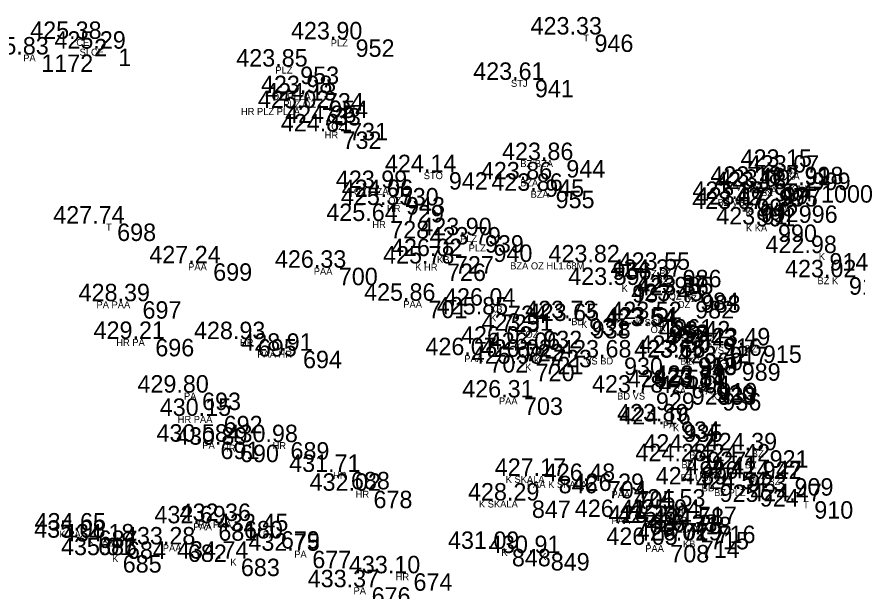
# Model space of a CAD drawing. Extents: x -639390 to -639075, y -1138747 to -1138358.
# Drawn here: x -639158.84 to -639122.71, y -1138672.58 to -1138647.88 of the extents above; entities that cross this region are included whole.
import ezdxf

# ---------------------------------------------------------------- set-up
doc = ezdxf.new("R2010")
doc.units = 0
for name, color, linetype in [('Vrstva 11', 7, 'Continuous'), ('Vrstva 12', 7, 'Continuous'), ('Vrstva 13', 7, 'Continuous'), ('Vrstva 57', 7, 'Continuous')]:
    doc.layers.add(name, color=color, linetype=linetype)

msp = doc.modelspace()

# ---------------------------------------------------------------- linework, layer by layer
at = {"layer": 'Vrstva 11'}
for p, q in [((-639134.28, -1138648.64), (-639134.28, -1138648.64)), ((-639155.79, -1138648.83), (-639155.79, -1138648.83)), ((-639144.55, -1138648.85), (-639144.55, -1138648.85)), ((-639154.75, -1138649.25), (-639154.75, -1138649.25)), ((-639158.06, -1138649.5), (-639158.06, -1138649.5)), ((-639146.93, -1138650.02), (-639146.93, -1138650.02)), ((-639136.84, -1138650.59), (-639136.84, -1138650.59)), ((-639145.87, -1138651.16), (-639145.87, -1138651.16)), ((-639145.69, -1138651.48), (-639145.69, -1138651.48)), ((-639146, -1138651.8), (-639146, -1138651.8)), ((-639144.83, -1138652.44), (-639144.83, -1138652.44)), ((-639145.11, -1138652.81), (-639145.11, -1138652.81)), ((-639135.49, -1138654.04), (-639135.49, -1138654.04)), ((-639125.25, -1138654.33), (-639125.25, -1138654.33)), ((-639140.54, -1138654.56), (-639140.54, -1138654.56)), ((-639136.4, -1138654.87), (-639136.4, -1138654.87)), ((-639124.94, -1138654.58), (-639124.94, -1138654.58)), ((-639142.65, -1138655.24), (-639142.65, -1138655.24)), ((-639126.55, -1138655.06), (-639126.55, -1138655.06)), ((-639126.19, -1138655.19), (-639126.19, -1138655.19)), ((-639124.54, -1138655.12), (-639124.54, -1138655.12)), ((-639135.95, -1138655.36), (-639135.95, -1138655.36)), ((-639126.35, -1138655.29), (-639126.35, -1138655.29)), ((-639142.43, -1138655.97), (-639142.43, -1138655.97)), ((-639142.38, -1138655.63), (-639142.38, -1138655.63)), ((-639127.32, -1138655.71), (-639127.32, -1138655.71)), ((-639127.18, -1138655.96), (-639127.18, -1138655.96)), ((-639127.33, -1138656.14), (-639127.33, -1138656.14)), ((-639125.5, -1138655.99), (-639125.5, -1138655.99)), ((-639143.06, -1138656.66), (-639143.06, -1138656.66)), ((-639154.8, -1138656.77), (-639154.8, -1138656.77)), ((-639126.39, -1138656.81), (-639126.39, -1138656.81)), ((-639138.99, -1138657.27), (-639138.99, -1138657.27)), ((-639138.62, -1138657.67), (-639138.62, -1138657.67)), ((-639124.18, -1138658.04), (-639124.18, -1138658.04)), ((-639150.67, -1138658.48), (-639150.67, -1138658.48)), ((-639140.62, -1138658.49), (-639140.62, -1138658.49)), ((-639140.28, -1138658.17), (-639140.28, -1138658.17)), ((-639133.51, -1138658.44), (-639133.51, -1138658.44)), ((-639145.27, -1138658.67), (-639145.27, -1138658.67)), ((-639130.49, -1138658.76), (-639130.49, -1138658.76)), ((-639130.84, -1138659.06), (-639130.84, -1138659.06)), ((-639123.34, -1138659.08), (-639123.34, -1138659.08)), ((-639132.66, -1138659.41), (-639132.66, -1138659.41)), ((-639129.74, -1138659.74), (-639129.74, -1138659.74)), ((-639129.67, -1138659.85), (-639129.67, -1138659.85)), ((-639153.71, -1138660.11), (-639153.71, -1138660.11)), ((-639141.42, -1138660.09), (-639141.42, -1138660.09)), ((-639138, -1138660.3), (-639138, -1138660.3)), ((-639129.95, -1138660.1), (-639129.95, -1138660.1)), ((-639138.31, -1138660.68), (-639138.31, -1138660.68)), ((-639134.51, -1138660.84), (-639134.51, -1138660.84)), ((-639134.4, -1138660.96), (-639134.4, -1138660.96)), ((-639130.85, -1138660.88), (-639130.85, -1138660.88)), ((-639136.48, -1138661.38), (-639136.48, -1138661.38)), ((-639131.1, -1138661.18), (-639131.1, -1138661.18)), ((-639131.03, -1138661.11), (-639131.03, -1138661.11)), ((-639153.16, -1138661.73), (-639153.16, -1138661.73)), ((-639148.75, -1138661.74), (-639148.75, -1138661.74)), ((-639128.76, -1138661.71), (-639128.76, -1138661.71)), ((-639137.27, -1138661.94), (-639137.27, -1138661.94)), ((-639128.48, -1138662.07), (-639128.48, -1138662.07)), ((-639127.04, -1138662.01), (-639127.04, -1138662.01)), ((-639146.81, -1138662.24), (-639146.81, -1138662.24)), ((-639138.8, -1138662.43), (-639138.8, -1138662.43)), ((-639136.06, -1138662.2), (-639136.06, -1138662.2)), ((-639129.57, -1138662.33), (-639129.57, -1138662.33)), ((-639136.81, -1138662.8), (-639136.81, -1138662.8)), ((-639136.43, -1138662.5), (-639136.43, -1138662.5)), ((-639133.01, -1138662.53), (-639133.01, -1138662.53)), ((-639129.83, -1138662.54), (-639129.83, -1138662.54)), ((-639129.8, -1138662.52), (-639129.8, -1138662.52)), ((-639127.95, -1138662.78), (-639127.95, -1138662.78)), ((-639130.1, -1138663.81), (-639130.1, -1138663.81)), ((-639129.06, -1138663.72), (-639129.06, -1138663.72)), ((-639128.99, -1138663.81), (-639128.99, -1138663.81)), ((-639128.95, -1138663.62), (-639128.95, -1138663.62)), ((-639151.15, -1138664.04), (-639151.15, -1138664.04)), ((-639137.31, -1138664.25), (-639137.31, -1138664.25)), ((-639131.64, -1138664.04), (-639131.64, -1138664.04)), ((-639128.78, -1138664.06), (-639128.78, -1138664.06)), ((-639150.22, -1138665.04), (-639150.22, -1138665.04)), ((-639130.56, -1138665.28), (-639130.56, -1138665.28)), ((-639130.45, -1138665.41), (-639130.45, -1138665.41)), ((-639150.36, -1138666.15), (-639150.36, -1138666.15)), ((-639149.52, -1138666.28), (-639149.52, -1138666.28)), ((-639147.35, -1138666.17), (-639147.35, -1138666.17)), ((-639129.43, -1138666.58), (-639129.43, -1138666.58)), ((-639126.75, -1138666.52), (-639126.75, -1138666.52)), ((-639129.77, -1138666.99), (-639129.77, -1138666.99)), ((-639127.05, -1138667), (-639127.05, -1138667)), ((-639144.75, -1138667.45), (-639144.75, -1138667.45)), ((-639135.82, -1138667.62), (-639135.82, -1138667.62)), ((-639133.71, -1138667.84), (-639133.71, -1138667.84)), ((-639127.7, -1138667.55), (-639127.7, -1138667.55)), ((-639125.68, -1138667.72), (-639125.68, -1138667.72)), ((-639143.78, -1138668.26), (-639143.78, -1138668.26)), ((-639128.9, -1138667.99), (-639128.9, -1138667.99)), ((-639127.17, -1138668.19), (-639127.17, -1138668.19)), ((-639132.47, -1138668.27), (-639132.47, -1138668.27)), ((-639136.97, -1138668.68), (-639136.97, -1138668.68)), ((-639129.83, -1138668.94), (-639129.83, -1138668.94)), ((-639124.83, -1138668.71), (-639124.83, -1138668.71)), ((-639150.45, -1138669.66), (-639150.45, -1138669.66)), ((-639149.35, -1138669.56), (-639149.35, -1138669.56)), ((-639132.47, -1138669.39), (-639132.47, -1138669.39)), ((-639131.03, -1138669.64), (-639131.03, -1138669.64)), ((-639130.49, -1138669.64), (-639130.49, -1138669.64)), ((-639130.06, -1138669.38), (-639130.06, -1138669.38)), ((-639155.6, -1138669.97), (-639155.6, -1138669.97)), ((-639147.76, -1138670), (-639147.76, -1138670)), ((-639129.31, -1138670.03), (-639129.31, -1138670.03)), ((-639129.03, -1138669.76), (-639129.03, -1138669.76)), ((-639155.62, -1138670.28), (-639155.62, -1138670.28)), ((-639129.71, -1138670.4), (-639129.71, -1138670.4)), ((-639154.38, -1138670.44), (-639154.38, -1138670.44)), ((-639151.76, -1138670.57), (-639151.76, -1138670.57)), ((-639137.83, -1138670.76), (-639137.83, -1138670.76)), ((-639131.02, -1138670.59), (-639131.02, -1138670.59)), ((-639154.56, -1138671.03), (-639154.56, -1138671.03)), ((-639146.41, -1138670.84), (-639146.41, -1138670.84)), ((-639136.16, -1138670.94), (-639136.16, -1138670.94)), ((-639149.48, -1138671.18), (-639149.48, -1138671.18)), ((-639142.06, -1138671.81), (-639142.06, -1138671.81)), ((-639143.86, -1138672.41), (-639143.86, -1138672.41))]:
    msp.add_line(p, q, dxfattribs=at)

# ---------------------------------------------------------------- texts
at = {"layer": 'Vrstva 12'}
for s, p in [('423.33 ', (-639136.749, -1138648.64)), ('425.38 ', (-639158.259, -1138648.83)), ('423.90 ', (-639147.049, -1138648.85)), ('425.83 ', (-639160.529, -1138649.5)), ('425.29 ', (-639157.219, -1138649.25)), ('423.85 ', (-639149.4, -1138650.02)), ('423.61 ', (-639139.215, -1138650.59)), ('423.98 ', (-639148.339, -1138651.16)), ('424.13 ', (-639148.159, -1138651.48)), ('425.02 ', (-639148.469, -1138651.8)), ('424.25 ', (-639147.3, -1138652.44)), ('424.81 ', (-639147.485, -1138652.81)), ('423.86 ', (-639137.976, -1138654.04)), ('424.14 ', (-639143.009, -1138654.56)), ('423.15 ', (-639127.72, -1138654.33)), ('423.86 ', (-639138.886, -1138654.87)), ('423.07 ', (-639127.409, -1138654.58)), ('423.99 ', (-639145.119, -1138655.24)), ('423.18 ', (-639129.019, -1138655.06)), ('423.13 ', (-639128.819, -1138655.29)), ('423.09 ', (-639128.659, -1138655.19)), ('422.91 ', (-639126.915, -1138655.12)), ('424.06 ', (-639144.866, -1138655.63)), ('423.86 ', (-639138.436, -1138655.36)), ('425.35 ', (-639144.9, -1138655.97)), ('423.18 ', (-639129.789, -1138655.71)), ('423.17 ', (-639129.649, -1138655.96)), ('422.97 ', (-639127.969, -1138655.99)), ('423.07 ', (-639129.799, -1138656.14)), ('425.64 ', (-639145.529, -1138656.66)), ('427.74 ', (-639157.269, -1138656.77)), ('423.01 ', (-639128.765, -1138656.81)), ('423.90 ', (-639141.489, -1138657.27)), ('423.79 ', (-639141.089, -1138657.67)), ('426.02 ', (-639142.749, -1138658.17)), ('422.98 ', (-639126.649, -1138658.04)), ('427.24 ', (-639153.139, -1138658.48)), ('425.78 ', (-639143.089, -1138658.49)), ('423.82 ', (-639135.979, -1138658.44)), ('426.33 ', (-639147.739, -1138658.67)), ('423.55 ', (-639132.96, -1138658.76)), ('424.37 ', (-639133.309, -1138659.06)), ('423.02 ', (-639125.809, -1138659.08)), ('423.59 ', (-639135.129, -1138659.41)), ('423.37 ', (-639132.209, -1138659.74)), ('423.36 ', (-639132.156, -1138659.85)), ('428.39 ', (-639156.179, -1138660.11)), ('425.86 ', (-639143.906, -1138660.09)), ('426.04 ', (-639140.469, -1138660.3)), ('423.43 ', (-639132.419, -1138660.1)), ('425.85 ', (-639140.78, -1138660.68)), ('423.73 ', (-639136.979, -1138660.84)), ('423.65 ', (-639136.87, -1138660.96)), ('423.52 ', (-639133.319, -1138660.88)), ('423.91 ', (-639138.855, -1138661.38)), ('423.54 ', (-639133.569, -1138661.18)), ('423.54 ', (-639133.499, -1138661.11)), ('429.21 ', (-639155.535, -1138661.73)), ('428.93 ', (-639151.219, -1138661.74)), ('423.42 ', (-639131.229, -1138661.71)), ('426.02 ', (-639139.739, -1138661.94)), ('423.43 ', (-639130.949, -1138662.07)), ('423.49 ', (-639129.509, -1138662.01)), ('428.91 ', (-639149.185, -1138662.24)), ('426.07 ', (-639141.269, -1138662.43)), ('426.02 ', (-639138.899, -1138662.5)), ('426.06 ', (-639138.546, -1138662.2)), ('423.56 ', (-639132.286, -1138662.52)), ('423.50 ', (-639132.069, -1138662.33)), ('425.98 ', (-639139.279, -1138662.8)), ('423.68 ', (-639135.479, -1138662.53)), ('423.65 ', (-639132.3, -1138662.54)), ('423.42 ', (-639130.419, -1138662.78)), ('423.75 ', (-639132.57, -1138663.81)), ('423.84 ', (-639131.459, -1138663.81)), ('423.81 ', (-639131.435, -1138663.72)), ('423.79 ', (-639131.419, -1138663.62)), ('429.80 ', (-639153.649, -1138664.04)), ('426.31 ', (-639139.685, -1138664.25)), ('423.78 ', (-639134.109, -1138664.04)), ('424.04 ', (-639131.249, -1138664.06)), ('430.15 ', (-639152.69, -1138665.04)), ('423.89 ', (-639133.029, -1138665.28)), ('424.16 ', (-639132.936, -1138665.41)), ('430.58 ', (-639152.829, -1138666.15)), ('430.89 ', (-639151.989, -1138666.28)), ('430.98 ', (-639149.819, -1138666.17)), ('424.22 ', (-639131.899, -1138666.58)), ('424.39 ', (-639129.219, -1138666.52)), ('424.28 ', (-639132.239, -1138666.99)), ('424.42 ', (-639129.519, -1138667)), ('431.71 ', (-639147.125, -1138667.45)), ('424.41 ', (-639130.075, -1138667.55)), ('427.17 ', (-639138.289, -1138667.62)), ('426.48 ', (-639136.179, -1138667.84)), ('424.47 ', (-639128.149, -1138667.72)), ('432.02 ', (-639146.249, -1138668.26)), ('426.29 ', (-639134.939, -1138668.27)), ('424.39 ', (-639131.369, -1138667.99)), ('424.54 ', (-639129.639, -1138668.19)), ('428.29 ', (-639139.439, -1138668.68)), ('424.53 ', (-639132.299, -1138668.94)), ('424.47 ', (-639127.299, -1138668.71)), ('426.41 ', (-639134.845, -1138669.39)), ('425.94 ', (-639132.529, -1138669.38)), ('432.69 ', (-639152.919, -1138669.66)), ('432.36 ', (-639151.836, -1138669.56)), ('426.11 ', (-639133.405, -1138669.64)), ('425.60 ', (-639132.989, -1138669.64)), ('434.65 ', (-639158.07, -1138669.97)), ('432.45 ', (-639150.23, -1138670)), ('426.33 ', (-639131.779, -1138670.03)), ('424.58 ', (-639131.499, -1138669.76)), ('435.08 ', (-639158.089, -1138670.28)), ('434.18 ', (-639156.849, -1138670.44)), ('426.02 ', (-639132.179, -1138670.4)), ('433.28 ', (-639154.229, -1138670.57)), ('431.09 ', (-639140.299, -1138670.76)), ('426.05 ', (-639133.49, -1138670.59)), ('435.01 ', (-639156.935, -1138671.03)), ('434.74 ', (-639151.949, -1138671.18)), ('432.75 ', (-639148.88, -1138670.84)), ('430.91 ', (-639138.535, -1138670.94)), ('433.10 ', (-639144.559, -1138671.81)), ('433.37 ', (-639146.329, -1138672.41))]:
    msp.add_text(s, height=0.75, dxfattribs=at).set_placement(p)
at = {"layer": 'Vrstva 13'}
for s, p in [(' 946', (-639134.28, -1138649.39)), (' 2', (-639155.79, -1138649.58)), (' 952', (-639144.55, -1138649.6)), (' 1', (-639154.75, -1138650)), (' 1172', (-639158.06, -1138650.25)), (' 953', (-639146.93, -1138650.77)), (' 941', (-639136.84, -1138651.34)), (' 734', (-639145.87, -1138651.91)), (' 954', (-639145.69, -1138652.23)), (' 733', (-639146, -1138652.55)), (' 731', (-639144.83, -1138653.19)), (' 732', (-639145.11, -1138653.56)), (' 944', (-639135.49, -1138654.79)), (' 998', (-639125.25, -1138655.08)), (' 942', (-639140.54, -1138655.31)), (' 945', (-639136.4, -1138655.62)), (' 999', (-639124.94, -1138655.33)), (' 730', (-639142.65, -1138655.99)), (' 994', (-639126.55, -1138655.81)), (' 997', (-639126.19, -1138655.94)), (' 1000', (-639124.54, -1138655.87)), (' 943', (-639142.38, -1138656.38)), (' 955', (-639135.95, -1138656.11)), (' 995', (-639126.35, -1138656.04)), (' 729', (-639142.43, -1138656.72)), (' 993', (-639127.32, -1138656.46)), (' 992', (-639127.18, -1138656.71)), (' 996', (-639125.5, -1138656.74)), (' 991', (-639127.33, -1138656.89)), (' 728', (-639143.06, -1138657.41)), (' 698', (-639154.8, -1138657.52)), (' 990', (-639126.39, -1138657.56)), (' 939', (-639138.99, -1138658.02)), (' 940', (-639138.62, -1138658.42)), (' 914', (-639124.18, -1138658.79)), (' 699', (-639150.67, -1138659.23)), (' 726', (-639140.62, -1138659.24)), (' 727', (-639140.28, -1138658.92)), (' 956', (-639133.51, -1138659.19)), (' 700', (-639145.27, -1138659.42)), (' 986', (-639130.49, -1138659.51)), (' 985', (-639130.84, -1138659.81)), (' 913', (-639123.34, -1138659.83)), (' 937', (-639132.66, -1138660.16)), (' 984', (-639129.74, -1138660.49)), (' 983', (-639129.67, -1138660.6)), (' 697', (-639153.71, -1138660.86)), (' 701', (-639141.42, -1138660.84)), (' 724', (-639138, -1138661.05)), (' 982', (-639129.95, -1138660.85)), (' 725', (-639138.31, -1138661.43)), (' 931', (-639134.51, -1138661.59)), (' 938', (-639134.4, -1138661.71)), (' 961', (-639130.85, -1138661.63)), (' 932', (-639136.48, -1138662.13)), (' 957', (-639131.1, -1138661.93)), (' 958', (-639131.03, -1138661.86)), (' 696', (-639153.16, -1138662.48)), (' 695', (-639148.75, -1138662.49)), (' 916', (-639128.76, -1138662.46)), (' 722', (-639137.27, -1138662.69)), (' 917', (-639128.48, -1138662.82)), (' 915', (-639127.04, -1138662.76)), (' 694', (-639146.81, -1138662.99)), (' 702', (-639138.8, -1138663.18)), (' 723', (-639136.06, -1138662.95)), (' 960', (-639129.57, -1138663.08)), (' 720', (-639136.81, -1138663.55)), (' 721', (-639136.43, -1138663.25)), (' 930', (-639133.01, -1138663.28)), (' 918', (-639129.83, -1138663.29)), (' 959', (-639129.8, -1138663.27)), (' 989', (-639127.95, -1138663.53)), (' 928', (-639130.1, -1138664.56)), (' 920', (-639129.06, -1138664.47)), (' 933', (-639128.99, -1138664.56)), (' 919', (-639128.95, -1138664.37)), (' 693', (-639151.15, -1138664.79)), (' 703', (-639137.31, -1138665)), (' 929', (-639131.64, -1138664.79)), (' 936', (-639128.78, -1138664.81)), (' 692', (-639150.22, -1138665.79)), (' 934', (-639130.56, -1138666.03)), (' 935', (-639130.45, -1138666.16)), (' 691', (-639150.36, -1138666.9)), (' 690', (-639149.52, -1138667.03)), (' 689', (-639147.35, -1138666.92)), (' 927', (-639129.43, -1138667.33)), (' 921', (-639126.75, -1138667.27)), (' 926', (-639129.77, -1138667.74)), (' 922', (-639127.05, -1138667.75)), (' 688', (-639144.75, -1138668.2)), (' 923', (-639127.7, -1138668.3)), (' 846', (-639135.82, -1138668.37)), (' 704', (-639133.71, -1138668.59)), (' 909', (-639125.68, -1138668.47)), (' 678', (-639143.78, -1138669.01)), (' 705', (-639132.47, -1138669.02)), (' 925', (-639128.9, -1138668.74)), (' 924', (-639127.17, -1138668.94)), (' 847', (-639136.97, -1138669.43)), (' 717', (-639129.83, -1138669.69)), (' 910', (-639124.83, -1138669.46)), (' 681', (-639150.45, -1138670.41)), (' 680', (-639149.35, -1138670.31)), (' 706', (-639132.47, -1138670.14)), (' 707', (-639131.03, -1138670.39)), (' 719', (-639130.49, -1138670.39)), (' 718', (-639130.06, -1138670.13)), (' 687', (-639155.6, -1138670.72)), (' 679', (-639147.76, -1138670.75)), (' 715', (-639129.31, -1138670.78)), (' 716', (-639129.03, -1138670.51)), (' 686', (-639155.62, -1138671.03)), (' 684', (-639154.38, -1138671.19)), (' 714', (-639129.71, -1138671.15)), (' 682', (-639151.76, -1138671.32)), (' 848', (-639137.83, -1138671.51)), (' 708', (-639131.02, -1138671.34)), (' 685', (-639154.56, -1138671.78)), (' 677', (-639146.41, -1138671.59)), (' 849', (-639136.16, -1138671.69)), (' 683', (-639149.48, -1138671.93)), (' 674', (-639142.06, -1138672.56)), (' 676', (-639143.86, -1138673.16))]:
    msp.add_text(s, height=0.75, dxfattribs=at).set_placement(p)
at = {"layer": 'Vrstva 57'}
for s, p in [('T', (-639134.48, -1138648.94)), ('CE', (-639156.277, -1138649.13)), ('PLZ', (-639145.339, -1138649.15)), ('SI CE', (-639156.138, -1138649.55)), ('PA', (-639158.56, -1138649.8)), ('PLZ', (-639147.719, -1138650.32)), ('STJ', (-639137.59, -1138650.89)), ('OZ PLZA', (-639147.87, -1138651.46)), ('PLZ OZ', (-639147.379, -1138651.78)), ('HR PLZ PLZA', (-639149.2, -1138652.1)), ('OZ', (-639145.319, -1138652.74)), ('HR', (-639145.599, -1138653.11)), ('BZ BZA', (-639137.19, -1138654.34)), ('BZ', (-639125.739, -1138654.63)), ('STO', (-639141.341, -1138654.86)), ('BZA', (-639137.2, -1138655.17)), ('BZ KA', (-639126.34, -1138654.88)), ('OZ OZA', (-639144.35, -1138655.54)), ('VS BZ', (-639127.939, -1138655.36)), ('KA', (-639126.69, -1138655.49)), ('KA K', (-639125.615, -1138655.42)), ('BZA', (-639136.75, -1138655.66)), ('BZ', (-639126.839, -1138655.59)), ('HR', (-639142.919, -1138656.27)), ('OZ', (-639142.869, -1138655.93)), ('BZ VS', (-639128.709, -1138656.01)), ('BZ', (-639127.669, -1138656.26)), ('K', (-639127.505, -1138656.44)), ('K KA', (-639126.6, -1138656.29)), ('HR', (-639143.549, -1138656.96)), ('T', (-639155, -1138657.07)), ('K KA', (-639127.49, -1138657.11)), ('PLZ', (-639139.779, -1138657.57)), ('PLZ', (-639139.409, -1138657.97)), ('K', (-639124.355, -1138658.34)), ('PAA', (-639151.47, -1138658.78)), ('K HR', (-639141.709, -1138658.79)), ('KB', (-639140.769, -1138658.47)), ('BZA OZ HL1.68M', (-639137.625, -1138658.74)), ('PAA', (-639146.07, -1138658.97)), ('OZ BZ', (-639131.879, -1138659.06)), ('BZ', (-639131.329, -1138659.36)), ('BZ K', (-639124.415, -1138659.38)), ('K', (-639132.835, -1138659.71)), ('OZ K', (-639130.815, -1138660.04)), ('OZ', (-639130.159, -1138660.15)), ('PA PAA', (-639155.41, -1138660.41)), ('PAA', (-639142.22, -1138660.39)), ('KB', (-639138.489, -1138660.6)), ('OZ', (-639130.439, -1138660.4)), ('K', (-639138.485, -1138660.98)), ('BD', (-639135.001, -1138661.14)), ('K', (-639134.575, -1138661.26)), ('K SCH', (-639132.225, -1138661.18)), ('OZ', (-639136.969, -1138661.68)), ('OZ', (-639131.589, -1138661.48)), ('K', (-639131.205, -1138661.41)), ('HR PA', (-639154.56, -1138662.03)), ('HR', (-639149.239, -1138662.04)), ('BZ K', (-639129.835, -1138662.01)), ('K', (-639137.445, -1138662.24)), ('VS', (-639128.969, -1138662.37)), ('BZ', (-639127.529, -1138662.31)), ('PAA HR', (-639148.499, -1138662.54)), ('PAA', (-639139.6, -1138662.73)), ('KB', (-639136.549, -1138662.5)), ('K', (-639129.745, -1138662.63)), ('K', (-639136.985, -1138663.1)), ('K', (-639136.605, -1138662.8)), ('VS BD', (-639134.401, -1138662.83)), ('BZ', (-639130.319, -1138662.84)), ('K', (-639129.975, -1138662.82)), ('BZA', (-639128.75, -1138663.08)), ('SA', (-639130.6, -1138664.11)), ('BZ', (-639129.549, -1138664.02)), ('PA', (-639129.49, -1138664.11)), ('BZ', (-639129.439, -1138663.92)), ('PA', (-639151.65, -1138664.34)), ('PAA', (-639138.11, -1138664.55)), ('BD VS', (-639133.029, -1138664.34)), ('K', (-639128.955, -1138664.36)), ('HR PAA', (-639151.92, -1138665.34)), ('PA', (-639131.06, -1138665.58)), ('K', (-639130.625, -1138665.71)), ('PA', (-639150.86, -1138666.45)), ('HR', (-639150.009, -1138666.58)), ('HR', (-639147.839, -1138666.47)), ('BD', (-639129.921, -1138666.88)), ('BZ', (-639127.239, -1138666.82)), ('BD', (-639130.261, -1138667.29)), ('BZ', (-639127.539, -1138667.3)), ('HR', (-639145.239, -1138667.75)), ('K SKALA', (-639137.82, -1138667.92)), ('PAA K SKALA', (-639136.91, -1138668.14)), ('BZ UDIRNA', (-639130.3, -1138667.85)), ('PLZ BZ', (-639127.369, -1138668.02)), ('HR', (-639144.269, -1138668.56)), ('BD', (-639129.391, -1138668.29)), ('BZ PLZ', (-639128.859, -1138668.49)), ('PAA', (-639133.27, -1138668.57)), ('K SKALA', (-639138.97, -1138668.98)), ('OZ BD', (-639131.221, -1138669.24)), ('T', (-639125.03, -1138669.01)), ('PAA', (-639151.25, -1138669.96)), ('PA PAA', (-639151.05, -1138669.86)), ('PAA', (-639133.27, -1138669.69)), ('PAA', (-639131.83, -1138669.94)), ('K', (-639130.665, -1138669.94)), ('KB', (-639130.549, -1138669.68)), ('K PAA', (-639157, -1138670.27)), ('PA', (-639148.26, -1138670.3)), ('PLZ OZ', (-639130.719, -1138670.06)), ('K', (-639129.485, -1138670.33)), ('K', (-639155.795, -1138670.58)), ('KB', (-639130.199, -1138670.7)), ('PAA', (-639155.18, -1138670.74)), ('PAA', (-639152.56, -1138670.87)), ('K', (-639138.005, -1138671.06)), ('PAA', (-639131.82, -1138670.89)), ('K', (-639154.735, -1138671.33)), ('PA', (-639146.91, -1138671.14)), ('K', (-639136.335, -1138671.24)), ('K', (-639149.655, -1138671.48)), ('HR', (-639142.549, -1138672.11)), ('PA', (-639144.36, -1138672.71))]:
    msp.add_text(s, height=0.3, dxfattribs=at).set_placement(p)

doc.saveas('drawing.dxf')
